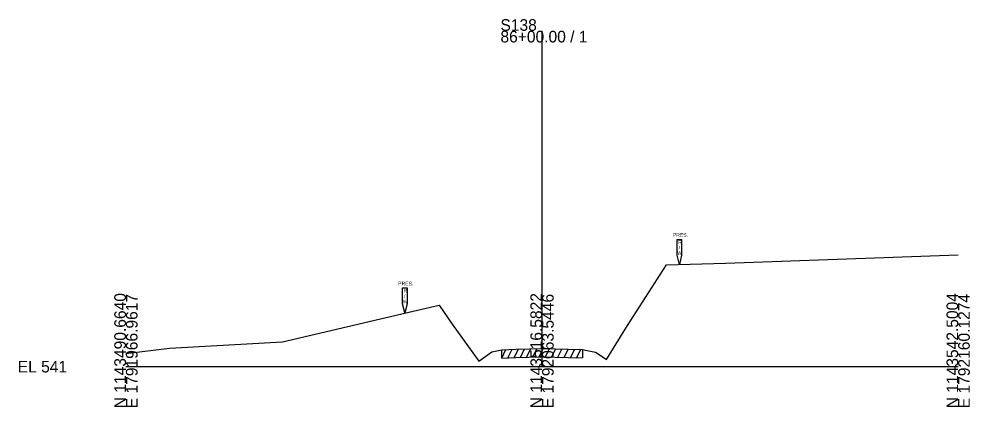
# Model space of a CAD drawing. Extents: x -26 to 1203, y -10 to 19606.
# Drawn here: x -25.7 to 202.8, y 11990.3 to 12083.6 of the extents above; entities that cross this region are included whole.
import ezdxf

# ---------------------------------------------------------------- set-up
doc = ezdxf.new("R2010")
doc.units = 0
for name, color, linetype in [('RD_EX_Driveway', 7, 'Continuous'), ('RD_GPK_XS_Cell', 7, 'Continuous'), ('RD_XS_ExGround', 7, 'Continuous'), ('RD_XS_ExPaveRet', 7, 'Continuous'), ('RD_XS_ExRW', 7, 'Continuous')]:
    doc.layers.add(name, color=color, linetype=linetype)

msp = doc.modelspace()

# ---------------------------------------------------------------- linework, layer by layer
at = {"layer": 'RD_GPK_XS_Cell'}
for p, q in [((100, 12000), (100, 12080.73)), ((0, 12000), (100, 12000)), ((100, 12000), (200, 12000))]:
    msp.add_line(p, q, dxfattribs=at)
at = {"layer": 'RD_XS_ExGround'}
msp.add_lwpolyline([(0, 12003.18), (10.51, 12004.47), (37.61, 12005.94), (69.04, 12013.38), (75.28, 12014.77), (78.38, 12010.19), (84.8, 12001.31), (85.93, 12002.1), (87.94, 12003.56), (89.55, 12003.9), (90.3, 12004.06), (93.73, 12004.2), (100.02, 12004.39), (106.31, 12004.17), (109.7, 12004.1), (110.88, 12003.85), (112.82, 12003.48), (114.67, 12002.3), (115.52, 12001.74), (120.54, 12009.87), (129.92, 12024.5), (144.1, 12024.89), (200, 12026.91)], dxfattribs=at)
at = {"layer": 'RD_XS_ExPaveRet'}
for p, q in [((90.3, 12002.06), (91.32, 12004.1)), ((90.3, 12002.06), (90.3, 12004.06)), ((91.8, 12002.12), (92.82, 12004.17)), ((93.3, 12002.19), (94.32, 12004.22)), ((94.8, 12002.24), (95.81, 12004.27)), ((96.3, 12002.28), (97.31, 12004.31)), ((97.8, 12002.33), (98.81, 12004.36)), ((99.3, 12002.37), (100.3, 12004.38)), ((100.8, 12002.37), (101.78, 12004.33)), ((102.3, 12002.31), (103.28, 12004.28)), ((103.8, 12002.26), (104.78, 12004.23)), ((105.3, 12002.21), (106.28, 12004.18)), ((106.8, 12002.16), (107.79, 12004.14)), ((108.3, 12002.13), (109.29, 12004.11)), ((109.7, 12004.1), (109.7, 12002.1)), ((90.3, 12002.06), (93.73, 12002.2)), ((93.73, 12002.2), (100.02, 12002.39)), ((100.02, 12002.39), (106.31, 12002.17)), ((106.31, 12002.17), (109.7, 12002.1))]:
    msp.add_line(p, q, dxfattribs=at)
at = {"layer": 'RD_XS_ExRW'}
for points in [[(132.45, 12030.6), (133.55, 12030.6), (133.55, 12026.77), (133, 12024.58), (132.45, 12026.77)], [(66.45, 12018.91), (67.55, 12018.91), (67.55, 12015.08), (67, 12012.9), (66.45, 12015.08)]]:
    msp.add_lwpolyline(points, close=True, dxfattribs=at)

# ---------------------------------------------------------------- texts
at = {"layer": 'RD_EX_Driveway'}
msp.add_text('543.20', height=0.0975, rotation=90, dxfattribs=at).set_placement((100.1, 12004.39))
at = {"layer": 'RD_GPK_XS_Cell'}
for s, p in [('S138', (90, 12080.73)), ('86+00.00 / 1', (90, 12077.93)), ('EL 541', (-26, 11998.6))]:
    msp.add_text(s, height=2.8, dxfattribs=at).set_placement(p)
for s, p in [('N 1143490.6640', (0, 11990)), ('E 1791966.9617', (2.8, 11990)), ('N 1143516.5822', (100, 11990)), ('E 1792063.5446', (102.8, 11990)), ('N 1143542.5004', (200, 11990)), ('E 1792160.1274', (202.8, 11990))]:
    msp.add_text(s, height=2.8, rotation=90, dxfattribs=at).set_placement(p)
at = {"layer": 'RD_XS_ExRW'}
for s, p in [('PRES.', (131.45, 12031.23)), ('R', (132.71, 12029.51)), ('W', (132.53, 12026.88)), ('/', (132.83, 12028.2)), ('PRES.', (65.45, 12019.54)), ('R', (66.71, 12017.82)), ('/', (66.83, 12016.51)), ('W', (66.53, 12015.2))]:
    msp.add_text(s, height=0.875, dxfattribs=at).set_placement(p)

doc.saveas('drawing.dxf')
